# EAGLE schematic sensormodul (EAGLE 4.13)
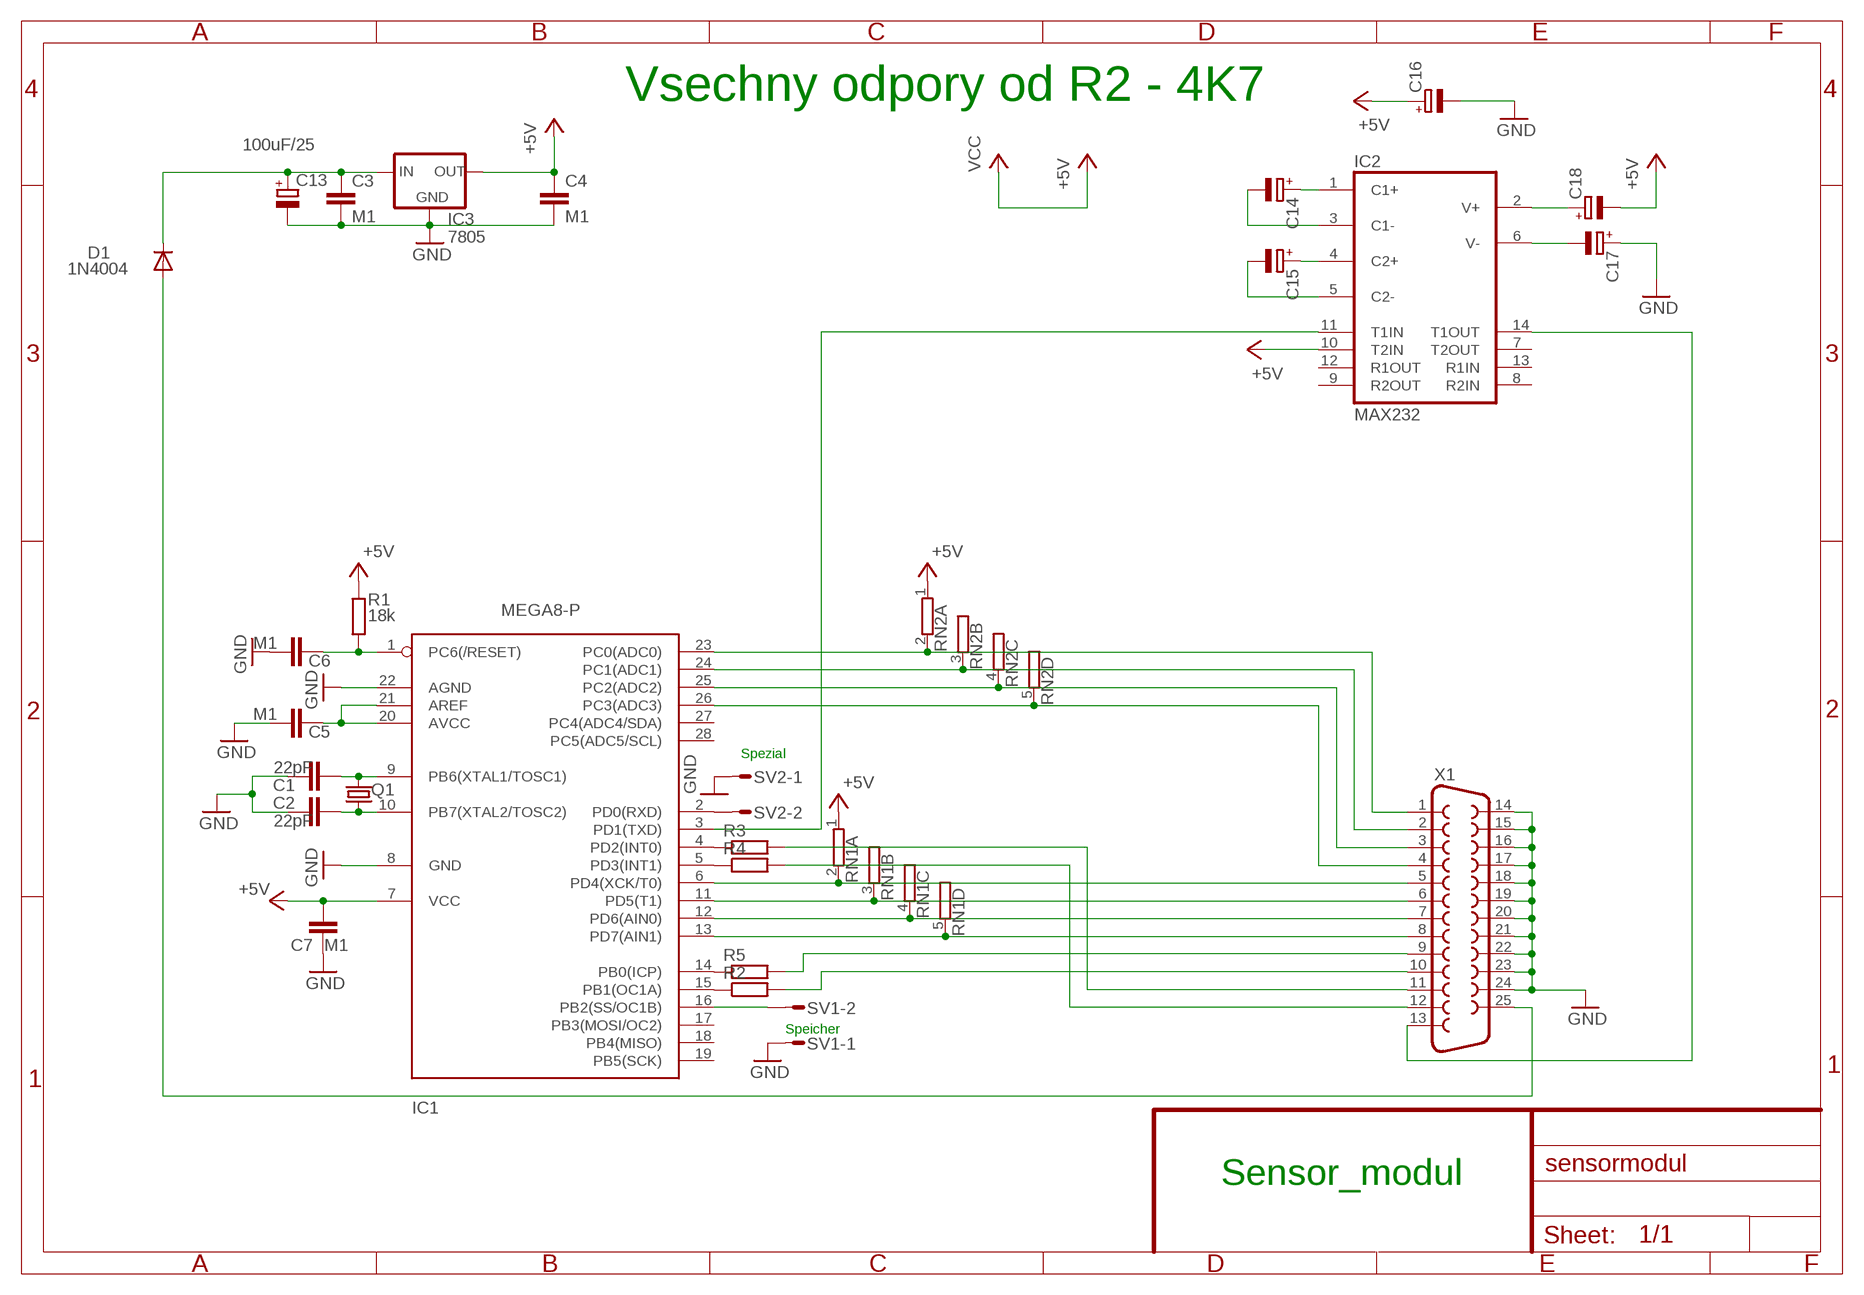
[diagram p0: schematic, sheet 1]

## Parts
C1  22pF  C-EU050-024X044  [C050-024X044]
C2  22pF  C-EU050-024X044  [C050-024X044]
C3  M1  C-EU050-024X044  [C050-024X044]
C4  M1  C-EU050-024X044  [C050-024X044]
C5  M1  C-EU050-024X044  [C050-024X044]
C6  M1  C-EU050-024X044  [C050-024X044]
C7  M1  C-EU050-024X044  [C050-024X044]
C13  100uF/25  CPOL-EUE5-6  [E5-6]
C14  CPOL-EUE5-4  [E5-4]
C15  CPOL-EUE5-4  [E5-4]
C16  CPOL-EUE5-4  [E5-4]
C17  CPOL-EUE5-4  [E5-4]
C18  CPOL-EUE5-4  [E5-4]
D1  1N4004  [DO41-10]
IC1  MEGA8-P  [DIL28-3]
IC2  MAX232  [DIL16]
IC3  7805  78XXS  [78XXS]
Q1  CRYTALHC49S  [HC49/S]
R1  18k  R-EU_0207/7  [0207/7]
R2  R-EU_0207/7  [0207/7]
R3  R-EU_0207/7  [0207/7]
R4  R-EU_0207/7  [0207/7]
R5  R-EU_0207/7  [0207/7]
RN1  GE04R  [SIL5]
RN2  GE04R  [SIL5]
SV1  L02P  [L02P]
SV2  L02P  [L02P]
X1  F25H  [F25H]

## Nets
+5V: C4.1 C7.2 C16.+ C18.- IC1.7(VCC) IC2.10(T2IN) IC3.OUT R1.1 RN1.1 RN2.1 ; supply symbol labelled VCC
GND: C1.1 C2.1 C3.2 C4.2 C5.1 C6.1 C7.1 C13.- C16.- C17.+ IC1.8(GND) IC1.22(AGND) IC3.GND SV1.1 SV2.1 X1.14 X1.15 X1.16 X1.17 X1.18 X1.19 X1.20 X1.21 X1.22 X1.23 X1.24
N$1: C2.2 IC1.10(PB7(XTAL2/TOSC2)) Q1.1
N$2: C1.2 IC1.9(PB6(XTAL1/TOSC1)) Q1.2
N$3: C5.2 IC1.20(AVCC) IC1.21(AREF)
N$4: D1.A X1.25
N$5: C15.+ IC2.4(C2+)
N$6: C14.+ IC2.1(C1+)
N$7: C18.+ IC2.2(V+)
N$8: C17.- IC2.6(V-)
N$9: C14.- IC2.3(C1-)
N$10: C15.- IC2.5(C2-)
N$11: IC1.23(PC0(ADC0)) RN2.2 X1.1
N$12: IC1.24(PC1(ADC1)) RN2.3 X1.2
N$13: C3.1 C13.+ D1.C IC3.IN
N$14: IC1.25(PC2(ADC2)) RN2.4 X1.3
N$15: IC1.26(PC3(ADC3)) RN2.5 X1.4
N$16: IC1.6(PD4(XCK/T0)) RN1.2 X1.5
N$17: IC1.11(PD5(T1)) RN1.3 X1.6
N$18: C6.2 IC1.1(PC6(/RESET)) R1.2
N$19: IC1.14(PB0(ICP)) R5.1
N$20: IC1.15(PB1(OC1A)) R2.1
N$21: IC1.4(PD2(INT0)) R3.1
N$22: IC1.5(PD3(INT1)) R4.1
N$23: IC1.12(PD6(AIN0)) RN1.4 X1.7
N$24: IC1.13(PD7(AIN1)) RN1.5 X1.8
N$25: R5.2 X1.9
N$26: R2.2 X1.10
N$27: R3.2 X1.11
N$28: R4.2 X1.12
N$29: IC1.3(PD1(TXD)) IC2.11(T1IN)
N$30: IC2.14(T1OUT) X1.13
N$31: IC1.16(PB2(SS/OC1B)) SV1.2
N$32: IC1.2(PD0(RXD)) SV2.2
Unconnected: IC1.17(PB3(MOSI/OC2)) IC1.18(PB4(MISO)) IC1.19(PB5(SCK)) IC1.27(PC4(ADC4/SDA)) IC1.28(PC5(ADC5/SCL)) IC2.7(T2OUT) IC2.8(R2IN) IC2.9(R2OUT) IC2.12(R1OUT) IC2.13(R1IN)

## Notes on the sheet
- Vsechny odpory od R2 - 4K7
- Spezial
- Speicher
- Sensor_modul

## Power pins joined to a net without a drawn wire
GND: IC2.15(GND)
VCC: IC2.16(VCC)

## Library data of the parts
C1-C7 = rcl:C-EU: CAPACITOR, European symbol
C13-C18 = rcl:CPOL-EU: POLARIZED CAPACITOR, European symbol
D1 = diode:1N4004: DIODE
IC1 = avr:MEGA8-P: MICROCONTROLLER 8 Kbytes FLASH 1 kbytes SRAM 512 bytes EEPROM USART 4-channel 10 bit ADC 2-channel 8 bit ADC
IC2 = maxim:MAX232: RS232 TRANSEIVER
IC3 = v-reg:78XXS: VOLTAGE REGULATOR
Q1 = crystal:CRYTAL: CRYSTAL
R1-R5 = rcl:R-EU_: RESISTOR, European symbol
RN1 RN2 = resistor-sil:GE04R: SIL RESISTOR
SV1 SV2 = con-amp-mt:L02P: AMP MT CONNECTOR
X1 = con-subd:F25: SUB-D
